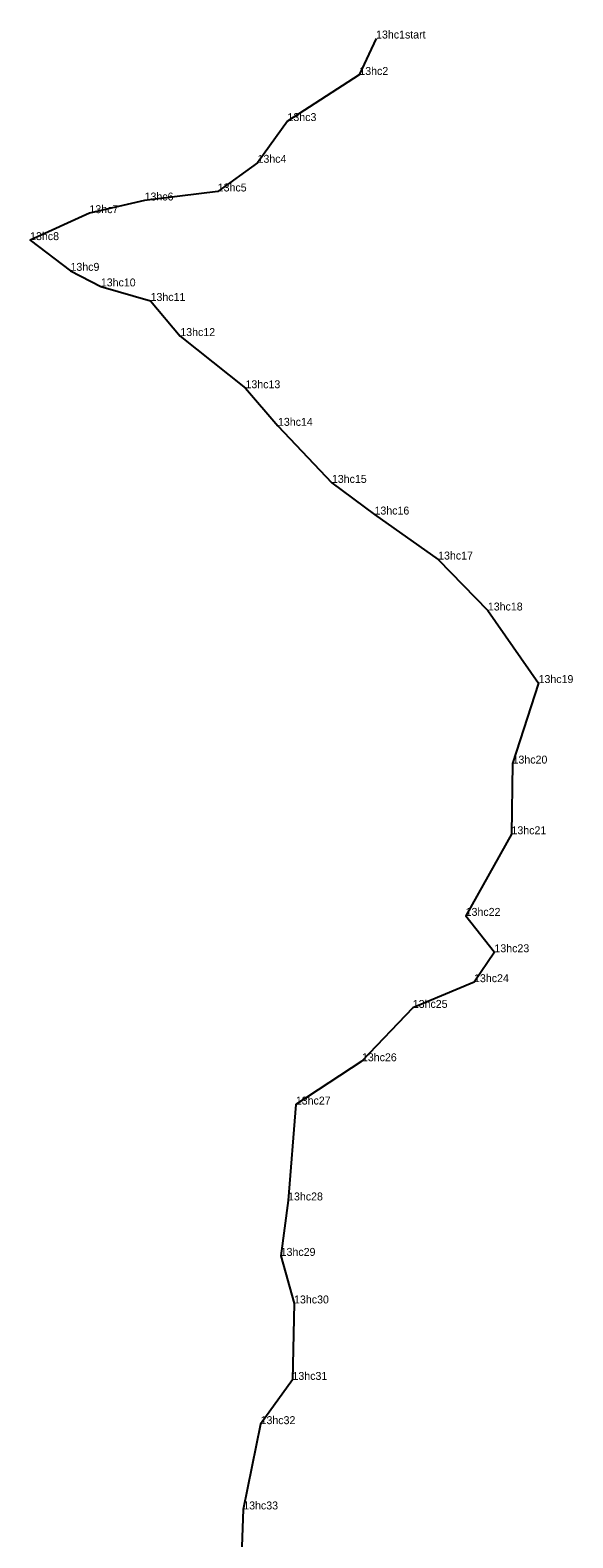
# Model space of a CAD drawing. Extents: x 2072529 to 2267990, y 436423 to 470008.
# Drawn here: x 2247880 to 2248223, y 446459 to 447409 of the extents above; entities that cross this region are included whole.
import ezdxf

# ---------------------------------------------------------------- set-up
doc = ezdxf.new("R2010")
doc.units = 0
doc.layers.add('Level 3', color=7, linetype='Continuous')
doc.layers.add('Old_Level_52', color=7, linetype='Continuous')

msp = doc.modelspace()

# ---------------------------------------------------------------- linework, layer by layer
at = {"layer": 'Level 3'}
for p, q in [((2248098.583, 447403.659), (2248098.583, 447403.659)), ((2248088.01, 447380.708), (2248088.01, 447380.708)), ((2248042.716, 447351.65), (2248042.716, 447351.65)), ((2248023.834, 447325.37), (2248023.834, 447325.37)), ((2247998.741, 447307.298), (2247998.741, 447307.298)), ((2247952.629, 447301.604), (2247952.629, 447301.604)), ((2247917.848, 447293.632), (2247917.848, 447293.632)), ((2247880.459, 447276.642), (2247880.459, 447276.642)), ((2247905.916, 447257.292), (2247905.916, 447257.292)), ((2247925.039, 447247.488), (2247925.039, 447247.488)), ((2247956.405, 447238.302), (2247956.405, 447238.302)), ((2247975.159, 447216.209), (2247975.159, 447216.209)), ((2248016.242, 447183.317), (2248016.242, 447183.317)), ((2248036.736, 447159.636), (2248036.736, 447159.636)), ((2248070.729, 447123.692), (2248070.729, 447123.692)), ((2248097.591, 447103.758), (2248097.591, 447103.758)), ((2248137.716, 447075.408), (2248137.716, 447075.408)), ((2248169.062, 447043.295), (2248169.062, 447043.295)), ((2248201.037, 446997.586), (2248201.037, 446997.586)), ((2248184.642, 446946.85), (2248184.642, 446946.85)), ((2248183.951, 446902.316), (2248183.951, 446902.316)), ((2248155.07, 446850.907), (2248155.07, 446850.907)), ((2248173.208, 446827.969), (2248173.208, 446827.969)), ((2248160.359, 446809.129), (2248160.359, 446809.129)), ((2248121.728, 446792.93), (2248121.728, 446792.93)), ((2248089.675, 446759.3), (2248089.675, 446759.3)), ((2248048.002, 446732.033), (2248048.002, 446732.033)), ((2248043.117, 446671.607), (2248043.117, 446671.607)), ((2248038.429, 446636.677), (2248038.429, 446636.677)), ((2248046.884, 446606.721), (2248046.884, 446606.721)), ((2248045.88, 446558.542), (2248045.88, 446558.542)), ((2248025.765, 446530.66), (2248025.765, 446530.66)), ((2248014.837, 446476.931), (2248014.837, 446476.931))]:
    msp.add_line(p, q, dxfattribs=at)
at = {"layer": 'Old_Level_52'}
msp.add_lwpolyline([(2248098.583, 447403.659), (2248088.01, 447380.708), (2248042.716, 447351.65), (2248023.834, 447325.37), (2247998.741, 447307.298), (2247952.629, 447301.604), (2247917.848, 447293.632), (2247880.459, 447276.642), (2247905.916, 447257.292), (2247925.039, 447247.488), (2247956.405, 447238.302), (2247975.159, 447216.209), (2248016.242, 447183.317), (2248036.736, 447159.636), (2248070.729, 447123.692), (2248097.591, 447103.758), (2248137.716, 447075.408), (2248169.062, 447043.295), (2248201.037, 446997.586), (2248184.642, 446946.85), (2248183.951, 446902.316), (2248155.07, 446850.907), (2248173.208, 446827.969), (2248160.359, 446809.129), (2248121.728, 446792.93), (2248089.675, 446759.3), (2248048.002, 446732.033), (2248043.117, 446671.607), (2248038.429, 446636.677), (2248046.884, 446606.721), (2248045.88, 446558.542), (2248025.765, 446530.66), (2248014.837, 446476.931), (2248013.36, 446435.932)], dxfattribs=at)

# ---------------------------------------------------------------- texts
for s, p in [('13hc1start', (2248098.583, 447403.659)), ('13hc2', (2248088.01, 447380.708)), ('13hc3', (2248042.716, 447351.65)), ('13hc4', (2248023.834, 447325.37)), ('13hc6', (2247952.629, 447301.604)), ('13hc5', (2247998.741, 447307.298)), ('13hc7', (2247917.848, 447293.632)), ('13hc8', (2247880.459, 447276.642)), ('13hc9', (2247905.916, 447257.292)), ('13hc10', (2247925.039, 447247.488)), ('13hc11', (2247956.405, 447238.302)), ('13hc12', (2247975.159, 447216.209)), ('13hc13', (2248016.242, 447183.317)), ('13hc14', (2248036.736, 447159.636)), ('13hc15', (2248070.729, 447123.692)), ('13hc16', (2248097.591, 447103.758)), ('13hc17', (2248137.716, 447075.408)), ('13hc18', (2248169.062, 447043.295)), ('13hc19', (2248201.037, 446997.586)), ('13hc20', (2248184.642, 446946.85)), ('13hc21', (2248183.951, 446902.316)), ('13hc22', (2248155.07, 446850.907)), ('13hc23', (2248173.208, 446827.969)), ('13hc24', (2248160.359, 446809.129)), ('13hc25', (2248121.728, 446792.93)), ('13hc26', (2248089.675, 446759.3)), ('13hc27', (2248048.002, 446732.033)), ('13hc28', (2248043.117, 446671.607)), ('13hc29', (2248038.429, 446636.677)), ('13hc30', (2248046.884, 446606.721)), ('13hc31', (2248045.88, 446558.542)), ('13hc32', (2248025.765, 446530.66)), ('13hc33', (2248014.837, 446476.931))]:
    msp.add_text(s, height=5).set_placement(p)

doc.saveas('drawing.dxf')
